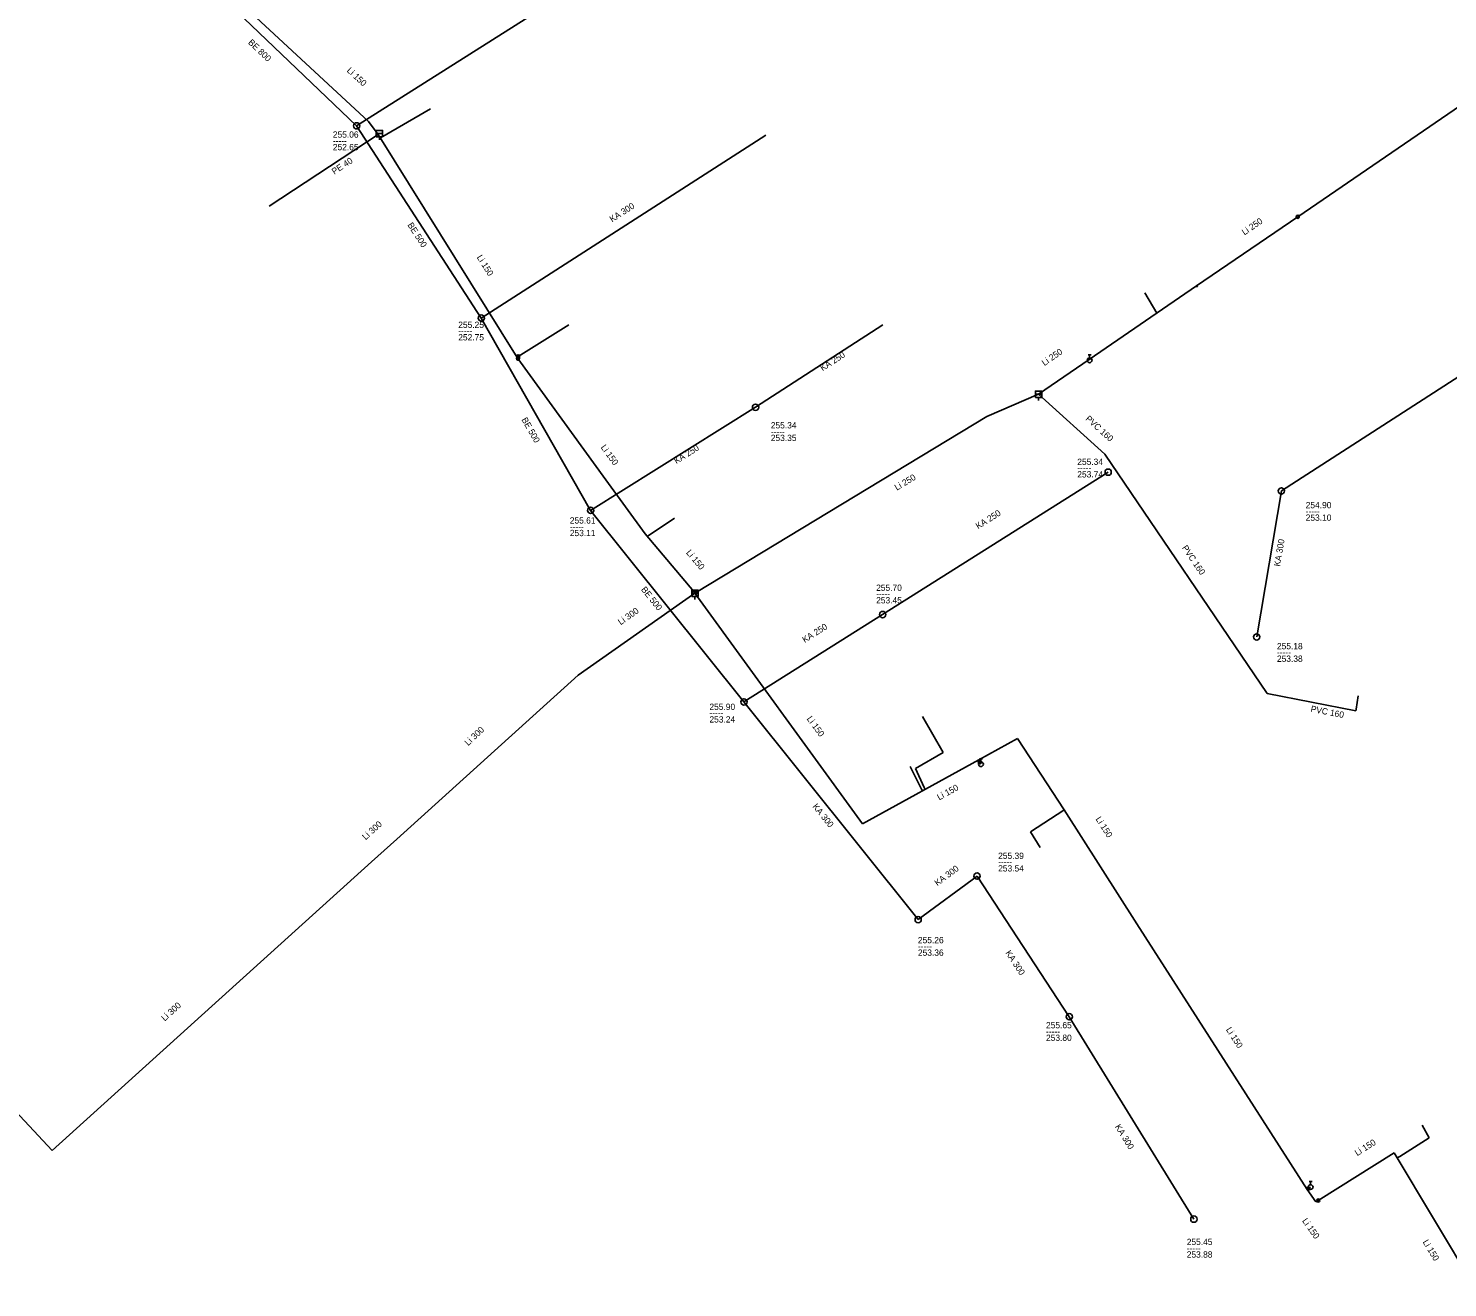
# Model space of a CAD drawing. Extents: x -647357 to -646700, y -1072205 to -1071664.
# Drawn here: x -647202.6 to -646977, y -1071986.7 to -1071786.5 of the extents above; entities that cross this region are included whole.
import ezdxf

# ---------------------------------------------------------------- set-up
doc = ezdxf.new("R2010")
doc.units = 0
for name, color, linetype in [('Level 19', 7, 'Continuous'), ('Level 20', 7, 'Continuous'), ('Level 21', 7, 'Continuous'), ('Level 24', 7, 'Continuous'), ('Level 26', 7, 'Continuous'), ('Level 29', 7, 'Continuous'), ('Level 40', 7, 'Continuous'), ('Level 41', 7, 'Continuous'), ('Level 44', 7, 'Continuous')]:
    doc.layers.add(name, color=color, linetype=linetype)

msp = doc.modelspace()

# ---------------------------------------------------------------- linework, layer by layer
at = {"layer": 'Level 19'}
for p, q in [((-647146.66, -1071803.89), (-647138.7, -1071799.25)), ((-647147, -1071803.34), (-647164.35, -1071814.73)), ((-647023.23, -1071831.79), (-647025.13, -1071828.53)), ((-647124.77, -1071838.64), (-647116.69, -1071833.65)), ((-647124.94, -1071838.8), (-647124.77, -1071838.64)), ((-647031.5, -1071854.22), (-647042.02, -1071844.66)), ((-647005.67, -1071892.25), (-647031.5, -1071854.22)), ((-647104.11, -1071867.16), (-647099.93, -1071864.36)), ((-647104.11, -1071867.16), (-647104.25, -1071867.28)), ((-646991.57, -1071895.03), (-647005.67, -1071892.25)), ((-646991.53, -1071894.75), (-646991.17, -1071892.63)), ((-647057.21, -1071901.64), (-647060.47, -1071895.89)), ((-646991.53, -1071894.75), (-646991.57, -1071895.03)), ((-647061.56, -1071904.19), (-647057.21, -1071901.64)), ((-647060.63, -1071907.48), (-647062.45, -1071903.87)), ((-647060.22, -1071907.19), (-647061.56, -1071904.19)), ((-647060.63, -1071907.48), (-647060.49, -1071907.74)), ((-647060.22, -1071907.19), (-647060.05, -1071907.5)), ((-647037.99, -1071910.81), (-647043.31, -1071914.28)), ((-647037.99, -1071910.81), (-647037.93, -1071910.76)), ((-647043.31, -1071914.28), (-647041.75, -1071916.76)), ((-646979.93, -1071962.9), (-646981.04, -1071960.89)), ((-646984.59, -1071965.87), (-646979.93, -1071962.9)), ((-646984.59, -1071965.87), (-646984.99, -1071966.11))]:
    msp.add_line(p, q, dxfattribs=at)
at = {"layer": 'Level 20'}
for p, q in [((-647148.55, -1071801.29), (-647182.34, -1071769.97)), ((-647000.79, -1071816.43), (-646958.2, -1071787.26)), ((-647147, -1071803.34), (-647148.55, -1071801.29)), ((-647124.94, -1071838.8), (-647147, -1071803.34)), ((-647016.89, -1071827.45), (-647000.79, -1071816.43)), ((-647016.89, -1071827.45), (-647033.97, -1071839.14)), ((-647016.89, -1071827.45), (-647016.72, -1071827.64)), ((-647124.79, -1071839), (-647124.94, -1071838.8)), ((-647110.8, -1071858.3), (-647124.79, -1071839)), ((-647033.97, -1071839.14), (-647042.01, -1071844.67)), ((-647033.97, -1071839.14), (-647033.89, -1071839.27)), ((-647050.22, -1071848.18), (-647042.01, -1071844.67)), ((-647096.43, -1071876.16), (-647050.22, -1071848.18)), ((-647104.58, -1071866.88), (-647110.8, -1071858.3)), ((-647096.85, -1071876.06), (-647104.58, -1071866.88)), ((-647115.22, -1071889.34), (-647096.65, -1071876.31)), ((-647096.65, -1071876.31), (-647096.85, -1071876.06)), ((-647096.65, -1071876.31), (-647096.43, -1071876.16)), ((-647069.99, -1071912.97), (-647096.65, -1071876.31)), ((-647144.07, -1071915.42), (-647115.22, -1071889.34)), ((-647051.5, -1071902.79), (-647045.34, -1071899.4)), ((-647045.34, -1071899.4), (-647037.93, -1071910.76)), ((-647051.5, -1071902.79), (-647069.99, -1071912.97)), ((-647051.5, -1071902.79), (-647051.37, -1071903.14)), ((-647051.37, -1071903.14), (-647051.17, -1071903.5)), ((-647037.93, -1071910.76), (-647026.37, -1071928.86)), ((-647148.07, -1071919.03), (-647144.07, -1071915.42)), ((-647198.86, -1071964.95), (-647148.07, -1071919.03)), ((-647026.37, -1071928.86), (-646999.32, -1071971.12)), ((-647209.23, -1071953.82), (-647198.86, -1071964.95)), ((-646997.54, -1071972.88), (-646985.48, -1071965.29)), ((-646972.64, -1071986.74), (-646985.48, -1071965.29)), ((-646999.13, -1071970.99), (-646999.32, -1071971.12)), ((-646997.92, -1071973.11), (-646999.32, -1071971.12)), ((-646999.13, -1071970.99), (-646998.75, -1071970.76)), ((-646997.54, -1071972.88), (-646997.92, -1071973.11))]:
    msp.add_line(p, q, dxfattribs=at)
at = {"layer": 'Level 21'}
for p, q in [((-647034.14, -1071838.395), (-647033.64, -1071838.395)), ((-647033.89, -1071838.895), (-647033.89, -1071838.395)), ((-647051.42, -1071902.625), (-647050.92, -1071902.625)), ((-647051.17, -1071903.125), (-647051.17, -1071902.625)), ((-646999, -1071969.885), (-646998.5, -1071969.885)), ((-646998.75, -1071970.385), (-646998.75, -1071969.885))]:
    msp.add_line(p, q, dxfattribs=at)
for centre in [(-647033.89, -1071839.27), (-647051.17, -1071903.5), (-646998.75, -1071970.76)]:
    msp.add_circle(centre, 0.375, dxfattribs=at)
at = {"layer": 'Level 26'}
for centre in [(-647000.81, -1071816.44), (-647124.79, -1071839), (-647124.77, -1071838.64), (-647096.85, -1071876.06), (-647096.43, -1071876.16), (-647051.37, -1071903.14), (-646999.13, -1071970.99), (-646997.54, -1071972.88)]:
    msp.add_circle(centre, 0.25, dxfattribs=at)
at = {"layer": 'Level 29'}
for p, q in [((-647146.82, -1071804.21), (-647146.82, -1071803.71)), ((-647042.01, -1071845.67), (-647042.01, -1071845.17)), ((-647096.65, -1071877.31), (-647096.65, -1071876.81))]:
    msp.add_line(p, q, dxfattribs=at)
for points in [[(-647147.32, -1071803.21), (-647147.32, -1071802.71), (-647146.32, -1071802.71), (-647146.32, -1071803.21)], [(-647042.51, -1071844.67), (-647042.51, -1071844.17), (-647041.51, -1071844.17), (-647041.51, -1071844.67)], [(-647097.15, -1071876.31), (-647097.15, -1071875.81), (-647096.15, -1071875.81), (-647096.15, -1071876.31)]]:
    msp.add_lwpolyline(points, dxfattribs=at)
for points in [[(-647147.32, -1071803.71), (-647146.32, -1071803.71), (-647146.32, -1071803.21), (-647147.32, -1071803.21)], [(-647042.51, -1071845.17), (-647041.51, -1071845.17), (-647041.51, -1071844.67), (-647042.51, -1071844.67)], [(-647097.15, -1071876.81), (-647096.15, -1071876.81), (-647096.15, -1071876.31), (-647097.15, -1071876.31)]]:
    msp.add_lwpolyline(points, close=True, dxfattribs=at)
at = {"layer": 'Level 40'}
for p, q in [((-647150.45, -1071801.98), (-647183.42, -1071770.44)), ((-647104.07, -1071772.57), (-647150.45, -1071801.98)), ((-647130.62, -1071832.55), (-647150.45, -1071801.98)), ((-647085.4, -1071803.46), (-647130.62, -1071832.55)), ((-647003.4, -1071860.04), (-646951.17, -1071826.32)), ((-647113.25, -1071863.13), (-647130.62, -1071832.55)), ((-647066.76, -1071833.65), (-647087.02, -1071846.74)), ((-647087.02, -1071846.74), (-647113.25, -1071863.13)), ((-647030.95, -1071857.06), (-647066.82, -1071879.7)), ((-647007.33, -1071883.26), (-647003.4, -1071860.04)), ((-647088.86, -1071893.6), (-647113.25, -1071863.13)), ((-647066.82, -1071879.7), (-647088.86, -1071893.6)), ((-647061.16, -1071928.22), (-647088.86, -1071893.6)), ((-647051.8, -1071921.29), (-647061.16, -1071928.22)), ((-647037.13, -1071943.66), (-647051.8, -1071921.29)), ((-647017.32, -1071975.85), (-647037.13, -1071943.66))]:
    msp.add_line(p, q, dxfattribs=at)
at = {"layer": 'Level 41'}
for centre in [(-647150.45, -1071801.98), (-647130.62, -1071832.55), (-647087.02, -1071846.74), (-647030.95, -1071857.06), (-647003.4, -1071860.04), (-647113.25, -1071863.13), (-647066.82, -1071879.7), (-647007.33, -1071883.26), (-647088.86, -1071893.6), (-647051.8, -1071921.29), (-647061.16, -1071928.22), (-647037.13, -1071943.66), (-647017.32, -1071975.85)]:
    msp.add_circle(centre, 0.5, dxfattribs=at)

# ---------------------------------------------------------------- texts
at = {"layer": 'Level 24'}
for s, rotation, p in [('Li 150', 317.173, (-647152.1, -1071793.29)), ('PE 40', 33.284, (-647154, -1071809.76)), ('Li 250', 34.391, (-647009.28, -1071819.42)), ('Li 150', 301.886, (-647131.39, -1071822.88)), ('Li 250', 34.521, (-647041.09, -1071840.2)), ('PVC 160', 317.737, (-647034.64, -1071848.69)), ('Li 150', 305.945, (-647111.69, -1071853.12)), ('Li 250', 30.854, (-647064.55, -1071860.02)), ('Li 150', 310.099, (-647098.13, -1071869.9)), ('PVC 160', 304.184, (-647019.26, -1071869.09)), ('Li 300', 35.056, (-647108.46, -1071881.42)), ('PVC 160', 348.846, (-646998.81, -1071895.14)), ('Li 150', 306.227, (-647078.93, -1071896.3)), ('Li 300', 43.46, (-647132.71, -1071900.64)), ('Li 150', 28.836, (-647057.82, -1071909.27)), ('Li 300', 42.066, (-647149.02, -1071915.61)), ('Li 150', 302.565, (-647032.99, -1071912.22)), ('Li 300', 42.117, (-647180.97, -1071944.43)), ('Li 150', 302.565, (-647012.26, -1071945.71)), ('Li 150', 32.184, (-646991.35, -1071965.85)), ('Li 150', 305.127, (-647000.16, -1071976.13)), ('Li 150', 300.905, (-646980.97, -1071979.48))]:
    msp.add_text(s, height=1, rotation=rotation, dxfattribs=at).set_placement(p)
at = {"layer": 'Level 44'}
for s, rotation, p in [('BE 800', 316.27, (-647167.78, -1071788.82)), ('KA 300', 32.753, (-647109.83, -1071817.35)), ('BE 500', 302.97, (-647142.41, -1071817.75)), ('KA 250', 32.867, (-647076.35, -1071841.03)), ('BE 500', 299.597, (-647124.27, -1071848.69)), ('KA 250', 31.999, (-647099.61, -1071855.78)), ('KA 250', 32.259, (-647051.62, -1071866.16)), ('KA 300', 80.394, (-647003.62, -1071872.11)), ('BE 500', 308.676, (-647105.28, -1071875.75)), ('KA 250', 32.238, (-647079.2, -1071884.23)), ('KA 300', 308.664, (-647078.02, -1071910.25)), ('KA 300', 36.516, (-647058.11, -1071922.91)), ('KA 300', 303.256, (-647047.34, -1071933.5)), ('KA 300', 301.608, (-647029.91, -1071961.14))]:
    msp.add_text(s, height=1, rotation=rotation, dxfattribs=at).set_placement(p)
for s, p in [('-----', (-647154.23, -1071804.86)), ('255.06', (-647154.23, -1071803.86)), ('252.65', (-647154.23, -1071805.86)), ('255.25', (-647134.29, -1071834.11)), ('-----', (-647134.29, -1071835.11)), ('252.75', (-647134.29, -1071836.11)), ('255.34', (-647084.59, -1071850.1)), ('-----', (-647084.59, -1071851.1)), ('253.35', (-647084.59, -1071852.1)), ('255.34', (-647035.86, -1071855.9)), ('-----', (-647035.86, -1071856.9)), ('253.74', (-647035.86, -1071857.9)), ('254.90', (-646999.54, -1071862.79)), ('255.61', (-647116.55, -1071865.23)), ('-----', (-646999.54, -1071863.79)), ('253.10', (-646999.54, -1071864.79)), ('-----', (-647116.55, -1071866.23)), ('253.11', (-647116.55, -1071867.23)), ('-----', (-647067.84, -1071876.93)), ('255.70', (-647067.84, -1071875.93)), ('253.45', (-647067.84, -1071877.93)), ('255.18', (-647004.11, -1071885.22)), ('-----', (-647004.11, -1071886.22)), ('253.38', (-647004.11, -1071887.22)), ('255.90', (-647094.35, -1071894.87)), ('-----', (-647094.35, -1071895.87)), ('253.24', (-647094.35, -1071896.87)), ('-----', (-647048.44, -1071919.56)), ('255.39', (-647048.44, -1071918.56)), ('253.54', (-647048.44, -1071920.56)), ('-----', (-647061.2, -1071932.97)), ('255.26', (-647061.2, -1071931.97)), ('253.36', (-647061.2, -1071933.97)), ('-----', (-647040.83, -1071946.5)), ('255.65', (-647040.83, -1071945.5)), ('253.80', (-647040.83, -1071947.5)), ('255.45', (-647018.45, -1071979.97)), ('-----', (-647018.45, -1071980.97)), ('253.88', (-647018.45, -1071981.97))]:
    msp.add_text(s, height=1, dxfattribs=at).set_placement(p)

doc.saveas('drawing.dxf')
